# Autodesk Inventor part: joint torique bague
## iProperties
Created: 2001-11
Part Number: joint torique bague
Material: Par défaut
Document SubType Name: Modélisation
Designer: User
Control State: 0
Master: False
Checked Out: False
Shininess: 20.0
Length Units: 11269
Angle Units: 11279
Time Units: 11290
Mass Units: 11283
Length Display Precision: 3
Angle Display Precision: 2
Density: 0.0
Volumn: 0.0
Area: 0.0
PropertySet Name: Model Information
Author: User
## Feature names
1. Révolution1 [Revolution]
